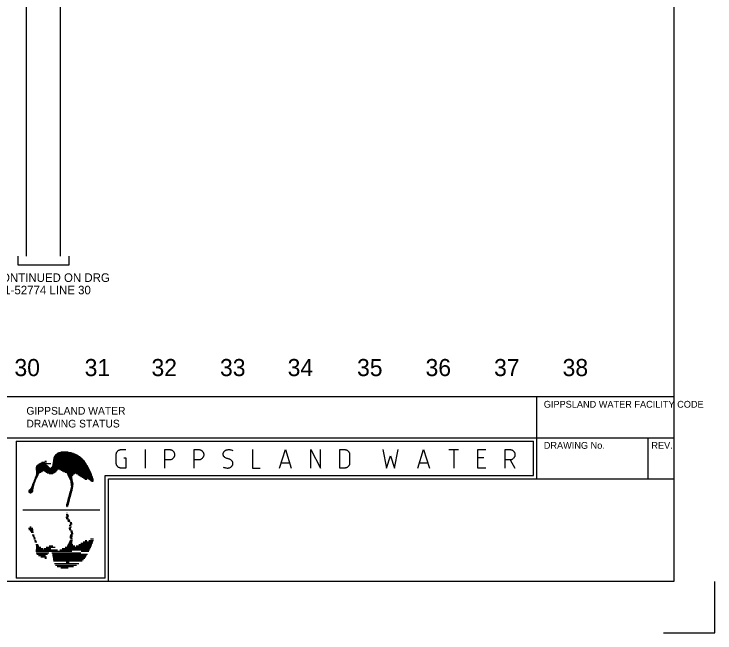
# Model space of a CAD drawing. Extents: x 0 to 841, y 0 to 594.
# Drawn here: x 636.4 to 841, y 0 to 180.7 of the extents above; entities that cross this region are included whole.
import ezdxf

# ---------------------------------------------------------------- set-up
doc = ezdxf.new("R2010")
doc.units = 0
doc.layers.add('A1BORDER', color=7, linetype='Continuous')
doc.layers.add('Level 1', color=7, linetype='Continuous')

msp = doc.modelspace()

# ---------------------------------------------------------------- linework, layer by layer
at = {"layer": 'A1BORDER'}
for p, q in [((829, 581), (829, 15)), ((592.5, 69), (829, 69)), ((789, 45), (789, 69)), ((28, 57), (829, 57)), ((637, 56), (788, 56)), ((637, 56), (637, 16)), ((788, 46), (788, 56)), ((821.5, 45), (821.5, 57)), ((648.03, 51.32), (655.85, 51.32)), ((648.12, 51.52), (655.59, 51.52)), ((648.23, 51.72), (655.31, 51.72)), ((648.37, 51.92), (655, 51.92)), ((648.53, 52.12), (654.64, 52.12)), ((648.74, 52.32), (654.24, 52.32)), ((649.02, 52.52), (653.76, 52.52)), ((649.39, 52.72), (653.15, 52.72)), ((650.01, 52.92), (652.2, 52.92)), ((643.26, 49.12), (645.9, 49.12)), ((643.54, 49.32), (645.57, 49.32)), ((643.85, 49.52), (647.09, 49.52)), ((644.18, 49.72), (645.89, 49.72)), ((644.54, 49.92), (645.36, 49.92)), ((645.37, 50.12), (645.86, 50.12)), ((647.63, 49.12), (657.68, 49.12)), ((647.66, 49.32), (657.57, 49.32)), ((647.69, 49.52), (657.44, 49.52)), ((647.71, 49.72), (657.31, 49.72)), ((647.75, 49.92), (657.17, 49.92)), ((647.78, 50.12), (657.02, 50.12)), ((647.81, 50.32), (656.86, 50.32)), ((647.85, 50.52), (656.69, 50.52)), ((647.88, 50.72), (656.5, 50.72)), ((647.91, 50.92), (656.3, 50.92)), ((647.96, 51.12), (656.08, 51.12)), ((642.73, 48.12), (658.25, 48.12)), ((642.74, 47.92), (658.35, 47.92)), ((642.75, 48.32), (646.79, 48.32)), ((642.79, 47.72), (649.08, 47.72)), ((642.81, 48.52), (646.55, 48.52)), ((642.83, 47.52), (648.95, 47.52)), ((642.85, 47.31), (644.88, 47.31)), ((642.87, 47.12), (644.57, 47.12)), ((642.9, 48.72), (646.37, 48.72)), ((643.04, 48.92), (646.16, 48.92)), ((645.14, 47.31), (648.83, 47.31)), ((645.49, 47.12), (648.67, 47.12)), ((647.19, 48.32), (658.14, 48.32)), ((647.42, 48.52), (658.03, 48.52)), ((647.54, 48.72), (657.92, 48.72)), ((647.61, 48.92), (657.8, 48.92)), ((649.72, 47.72), (658.45, 47.72)), ((650.12, 47.52), (658.55, 47.52)), ((650.48, 47.31), (658.64, 47.31)), ((650.87, 47.12), (658.73, 47.12)), ((642.43, 45.12), (642.9, 45.12)), ((642.5, 45.32), (643, 45.32)), ((642.57, 45.52), (643.1, 45.52)), ((642.65, 45.72), (643.2, 45.72)), ((642.72, 45.92), (643.3, 45.92)), ((642.79, 46.12), (643.4, 46.12)), ((642.84, 46.32), (643.5, 46.32)), ((642.87, 46.52), (643.6, 46.52)), ((642.88, 46.92), (644.23, 46.92)), ((642.88, 46.72), (643.83, 46.72)), ((645.76, 46.92), (648.42, 46.92)), ((646.05, 46.72), (648.11, 46.72)), ((646.62, 46.52), (647.67, 46.52)), ((651.36, 46.92), (658.82, 46.92)), ((651.76, 46.72), (658.9, 46.72)), ((651.88, 46.52), (654.15, 46.52)), ((651.99, 46.32), (653.71, 46.32)), ((652.1, 46.12), (653.52, 46.12)), ((652.2, 45.92), (653.4, 45.92)), ((652.31, 45.72), (653.33, 45.72)), ((652.41, 45.52), (653.31, 45.52)), ((652.5, 45.32), (653.34, 45.32)), ((652.6, 45.12), (653.38, 45.12)), ((654.57, 46.52), (658.99, 46.52)), ((655, 46.32), (659.07, 46.32)), ((655.31, 46.12), (659.14, 46.12)), ((655.62, 45.92), (659.22, 45.92)), ((655.93, 45.72), (659.29, 45.72)), ((656.24, 45.52), (659.35, 45.52)), ((656.55, 45.32), (659.42, 45.32)), ((656.86, 45.12), (657.74, 45.12)), ((657.91, 45.12), (659.48, 45.12)), ((663, 46), (788, 46)), ((663, 16), (663, 46)), ((641.64, 43.12), (642.25, 43.12)), ((641.73, 43.32), (642.3, 43.32)), ((641.82, 43.51), (642.35, 43.51)), ((641.91, 43.72), (642.41, 43.72)), ((641.99, 43.92), (642.48, 43.92)), ((642.06, 44.12), (642.55, 44.12)), ((642.13, 44.32), (642.62, 44.32)), ((642.21, 44.52), (642.69, 44.52)), ((642.28, 44.72), (642.76, 44.72)), ((642.35, 44.92), (642.83, 44.92)), ((652.69, 44.92), (653.41, 44.92)), ((652.78, 44.72), (653.44, 44.72)), ((652.83, 44.52), (653.48, 44.52)), ((652.86, 44.32), (653.53, 44.32)), ((652.89, 44.12), (653.57, 44.12)), ((652.91, 43.92), (653.62, 43.92)), ((652.94, 43.72), (653.67, 43.72)), ((652.97, 43.51), (653.71, 43.51)), ((653, 43.32), (653.69, 43.32)), ((653.02, 43.12), (653.67, 43.12)), ((657.17, 44.92), (657.68, 44.92)), ((657.51, 44.72), (657.54, 44.72)), ((658.19, 44.92), (659.54, 44.92)), ((658.47, 44.72), (659.59, 44.72)), ((658.75, 44.52), (659.58, 44.52)), ((659.02, 44.32), (659.47, 44.32)), ((664, 45), (829, 45)), ((664, 15), (664, 45)), ((640.62, 41.32), (641.88, 41.32)), ((640.63, 41.52), (641.93, 41.52)), ((640.72, 41.12), (641.73, 41.12)), ((640.73, 41.72), (641.95, 41.72)), ((640.9, 41.92), (641.97, 41.92)), ((641.1, 42.12), (642, 42.12)), ((641.25, 42.31), (642.04, 42.31)), ((641.37, 42.52), (642.09, 42.52)), ((641.46, 42.72), (642.15, 42.72)), ((641.55, 42.92), (642.2, 42.92)), ((652.63, 41.12), (653.26, 41.12)), ((652.68, 41.32), (653.31, 41.32)), ((652.74, 41.52), (653.37, 41.52)), ((652.79, 41.72), (653.41, 41.72)), ((652.85, 41.92), (653.45, 41.92)), ((652.9, 42.12), (653.49, 42.12)), ((652.95, 42.31), (653.53, 42.31)), ((652.99, 42.52), (653.57, 42.52)), ((653.03, 42.72), (653.61, 42.72)), ((653.05, 42.92), (653.64, 42.92)), ((641.03, 40.92), (641.43, 40.92)), ((652.03, 38.92), (652.66, 38.92)), ((652.09, 39.12), (652.72, 39.12)), ((652.14, 39.32), (652.77, 39.32)), ((652.2, 39.52), (652.82, 39.52)), ((652.25, 39.72), (652.88, 39.72)), ((652.3, 39.92), (652.93, 39.92)), ((652.36, 40.12), (652.99, 40.12)), ((652.41, 40.32), (653.04, 40.32)), ((652.47, 40.52), (653.1, 40.52)), ((652.52, 40.72), (653.15, 40.72)), ((652.57, 40.92), (653.2, 40.92)), ((651.63, 37.32), (652.23, 37.32)), ((651.64, 37.12), (652.17, 37.12)), ((651.65, 37.52), (652.28, 37.52)), ((651.71, 37.72), (652.34, 37.72)), ((651.76, 37.92), (652.39, 37.92)), ((651.79, 36.92), (651.9, 36.92)), ((651.82, 38.12), (652.44, 38.12)), ((651.87, 38.32), (652.5, 38.32)), ((651.92, 38.52), (652.55, 38.52)), ((651.98, 38.72), (652.61, 38.72)), ((638.93, 35.98), (661.47, 35.98)), ((651.79, 35.04), (651.9, 35.04)), ((651.54, 33.84), (652.17, 33.84)), ((651.63, 34.64), (652.23, 34.64)), ((651.65, 33.44), (652.28, 33.44)), ((651.71, 34.24), (652.34, 34.24)), ((652.03, 33.04), (652.66, 33.04)), ((641.03, 31.04), (641.43, 31.04)), ((652.14, 32.64), (652.77, 32.64)), ((652.47, 31.44), (653.1, 31.44)), ((652.57, 31.04), (653.2, 31.04)), ((652.66, 32.24), (653.29, 32.24)), ((652.77, 31.84), (653.4, 31.84)), ((640.62, 30.64), (641.88, 30.64)), ((640.73, 30.24), (641.95, 30.24)), ((641.1, 29.84), (642, 29.84)), ((641.37, 29.44), (642.09, 29.44)), ((652.34, 30.64), (652.97, 30.64)), ((652.45, 30.24), (653.07, 30.24)), ((652.9, 29.84), (653.49, 29.84)), ((652.99, 29.44), (653.57, 29.44)), ((653.05, 29.04), (653.64, 29.04)), ((641.73, 28.64), (642.3, 28.64)), ((641.91, 28.24), (642.41, 28.24)), ((642.06, 27.84), (642.55, 27.84)), ((642.21, 27.44), (642.69, 27.44)), ((642.35, 27.04), (642.83, 27.04)), ((642.5, 26.64), (643, 26.64)), ((652.5, 26.64), (653.34, 26.64)), ((652.66, 27.84), (653.35, 27.84)), ((652.69, 27.04), (653.41, 27.04)), ((652.72, 28.24), (653.44, 28.24)), ((652.77, 28.64), (653.46, 28.64)), ((652.83, 27.44), (653.48, 27.44)), ((656.55, 26.64), (659.42, 26.64)), ((657.17, 27.04), (657.68, 27.04)), ((658.19, 27.04), (659.54, 27.04)), ((658.75, 27.44), (659.58, 27.44)), ((642.79, 25.84), (643.4, 25.84)), ((642.85, 24.65), (644.88, 24.65)), ((642.87, 25.44), (643.6, 25.44)), ((642.88, 25.04), (644.23, 25.04)), ((645.14, 24.65), (647.18, 24.65)), ((645.76, 25.04), (648.42, 25.04)), ((646.62, 25.44), (647.67, 25.44)), ((650.48, 24.65), (658.64, 24.65)), ((651.36, 25.04), (658.82, 25.04)), ((651.88, 25.44), (654.15, 25.44)), ((652.1, 25.84), (653.52, 25.84)), ((652.31, 26.24), (653.33, 26.24)), ((654.57, 25.44), (658.99, 25.44)), ((655.31, 25.84), (659.14, 25.84)), ((655.93, 26.24), (659.29, 26.24)), ((642.73, 23.84), (653.27, 23.84)), ((642.79, 24.24), (649.08, 24.24)), ((642.81, 23.44), (646.55, 23.44)), ((643.04, 23.04), (646.16, 23.04)), ((643.54, 22.64), (645.57, 22.64)), ((647.42, 23.44), (655.89, 23.44)), ((647.61, 23.04), (657.8, 23.04)), ((647.66, 22.64), (657.57, 22.64)), ((649.72, 24.24), (658.45, 24.24)), ((655.94, 23.84), (658.25, 23.84)), ((644.18, 22.24), (645.89, 22.24)), ((645.37, 21.84), (645.86, 21.84)), ((647.71, 22.24), (657.31, 22.24)), ((647.78, 21.84), (657.02, 21.84)), ((647.85, 21.44), (656.69, 21.44)), ((647.91, 21.04), (656.3, 21.04)), ((651.57, 20.64), (652.44, 20.64)), ((648.23, 20.24), (655.31, 20.24)), ((648.53, 19.84), (654.64, 19.84)), ((649.02, 19.44), (653.76, 19.44)), ((650.01, 19.04), (652.2, 19.04)), ((829, 15), (28, 15)), ((663, 16), (637, 16)), ((829, 15), (829, 15)), ((841, 0), (841, 15)), ((826, 0), (841, 0))]:
    msp.add_line(p, q, dxfattribs=at)
for points in [[(668.49, 51.15), (669.06, 51.15), (669.06, 48.16), (667.64, 48.16), (667.51, 48.16), (667.39, 48.18), (667.28, 48.21), (667.15, 48.25), (667.04, 48.3), (666.93, 48.36), (666.82, 48.43), (666.73, 48.51), (666.64, 48.6), (666.55, 48.7), (666.48, 48.8), (666.41, 48.91), (666.35, 49.02), (666.31, 49.14), (666.27, 49.27), (666.24, 49.39), (666.22, 49.52), (666.22, 49.66), (666.22, 52.05), (666.22, 52.18), (666.24, 52.31), (666.27, 52.43), (666.31, 52.56), (666.35, 52.67), (666.41, 52.79), (666.48, 52.9), (666.55, 53), (666.64, 53.1), (666.73, 53.19), (666.82, 53.27), (666.93, 53.34), (667.04, 53.4), (667.15, 53.45), (667.28, 53.49), (667.39, 53.52), (667.51, 53.54), (667.64, 53.54), (669.06, 53.54)], [(674.74, 48.16), (674.74, 53.54)], [(680.42, 48.16), (680.42, 53.54), (681.84, 53.54), (681.96, 53.54), (682.08, 53.52), (682.2, 53.49), (682.32, 53.45), (682.43, 53.4), (682.54, 53.34), (682.65, 53.27), (682.74, 53.19), (682.84, 53.1), (682.92, 53), (682.99, 52.9), (683.06, 52.79), (683.12, 52.67), (683.17, 52.56), (683.21, 52.43), (683.23, 52.31), (683.25, 52.18), (683.26, 52.05), (683.25, 51.91), (683.23, 51.78), (683.21, 51.66), (683.17, 51.53), (683.12, 51.42), (683.06, 51.3), (682.99, 51.19), (682.92, 51.09), (682.84, 50.99), (682.74, 50.9), (682.65, 50.82), (682.54, 50.75), (682.43, 50.69), (682.32, 50.64), (682.2, 50.6), (682.08, 50.57), (681.96, 50.55), (681.84, 50.55), (680.42, 50.55)], [(688.93, 48.16), (688.93, 53.54), (690.35, 53.54), (690.47, 53.54), (690.59, 53.52), (690.71, 53.49), (690.83, 53.45), (690.94, 53.4), (691.05, 53.34), (691.16, 53.27), (691.26, 53.19), (691.35, 53.1), (691.43, 53), (691.51, 52.9), (691.57, 52.79), (691.63, 52.67), (691.68, 52.56), (691.72, 52.43), (691.75, 52.31), (691.76, 52.18), (691.77, 52.05), (691.76, 51.91), (691.75, 51.78), (691.72, 51.66), (691.68, 51.53), (691.63, 51.42), (691.57, 51.3), (691.51, 51.19), (691.43, 51.09), (691.35, 50.99), (691.26, 50.9), (691.16, 50.82), (691.05, 50.75), (690.94, 50.69), (690.83, 50.64), (690.71, 50.6), (690.59, 50.57), (690.47, 50.55), (690.35, 50.55), (688.93, 50.55)], [(697.45, 48.46), (697.67, 48.36), (697.9, 48.27), (698.12, 48.21), (698.36, 48.17), (698.6, 48.16), (698.84, 48.16), (698.87, 48.16), (699.03, 48.18), (699.18, 48.21), (699.33, 48.26), (699.48, 48.32), (699.62, 48.4), (699.72, 48.46), (699.81, 48.53), (699.9, 48.61), (699.98, 48.69), (700.05, 48.78), (700.11, 48.88), (700.17, 48.99), (700.22, 49.09), (700.25, 49.21), (700.28, 49.32), (700.29, 49.36), (700.3, 49.44), (700.3, 49.52), (700.3, 49.61), (700.29, 49.69), (700.27, 49.77), (700.25, 49.86), (700.22, 49.93), (700.18, 50.01), (700.14, 50.09), (700.09, 50.15), (700.04, 50.21), (700.01, 50.25), (699.85, 50.39), (699.69, 50.51), (699.52, 50.61), (699.34, 50.7), (699.15, 50.78), (698.95, 50.83), (698.87, 50.85), (698.68, 50.9), (698.49, 50.96), (698.3, 51.04), (698.12, 51.14), (697.96, 51.26), (697.8, 51.39), (697.73, 51.45), (697.67, 51.51), (697.62, 51.57), (697.58, 51.64), (697.53, 51.71), (697.5, 51.79), (697.47, 51.87), (697.46, 51.95), (697.44, 52.04), (697.43, 52.12), (697.43, 52.21), (697.44, 52.29), (697.45, 52.35), (697.47, 52.46), (697.51, 52.58), (697.55, 52.69), (697.61, 52.79), (697.67, 52.89), (697.74, 52.99), (697.82, 53.07), (697.9, 53.15), (697.99, 53.23), (698.02, 53.24), (698.15, 53.33), (698.3, 53.4), (698.44, 53.45), (698.6, 53.5), (698.75, 53.52), (698.87, 53.54), (699.11, 53.55), (699.35, 53.53), (699.58, 53.49), (699.82, 53.43), (700.04, 53.35), (700.27, 53.25)], [(705.96, 53.54), (705.96, 48.16), (708.23, 48.16)], [(713.91, 48.16), (715.61, 53.54), (717.32, 48.16)], [(722.99, 48.16), (722.99, 53.54), (725.83, 48.16), (725.83, 53.54)], [(731.52, 48.16), (731.52, 53.54), (732.94, 53.54), (733.06, 53.54), (733.18, 53.52), (733.3, 53.49), (733.42, 53.45), (733.53, 53.4), (733.64, 53.34), (733.75, 53.27), (733.84, 53.19), (733.94, 53.1), (734.02, 53), (734.09, 52.9), (734.16, 52.79), (734.22, 52.67), (734.27, 52.56), (734.31, 52.43), (734.33, 52.31), (734.35, 52.18), (734.36, 52.05), (734.36, 49.66), (734.35, 49.52), (734.33, 49.39), (734.31, 49.27), (734.27, 49.14), (734.22, 49.02), (734.16, 48.91), (734.09, 48.8), (734.02, 48.7), (733.94, 48.6), (733.84, 48.51), (733.75, 48.43), (733.64, 48.36), (733.53, 48.3), (733.42, 48.25), (733.3, 48.21), (733.18, 48.18), (733.06, 48.16), (732.94, 48.16), (731.52, 48.16)], [(744.01, 53.54), (745.14, 48.16), (746.28, 51.75), (747.41, 48.16), (748.55, 53.54)], [(754.22, 48.16), (755.92, 53.54), (757.63, 48.16)], [(763.31, 53.54), (766.15, 53.54)], [(764.73, 53.54), (764.73, 48.16)], [(774.09, 48.16), (771.82, 48.16), (771.82, 53.54), (774.09, 53.54)], [(779.78, 48.16), (779.78, 53.54), (781.2, 53.54), (781.32, 53.54), (781.44, 53.52), (781.56, 53.49), (781.68, 53.45), (781.79, 53.4), (781.9, 53.34), (782.01, 53.27), (782.1, 53.19), (782.2, 53.1), (782.28, 53), (782.35, 52.9), (782.42, 52.79), (782.48, 52.67), (782.53, 52.56), (782.56, 52.43), (782.59, 52.31), (782.61, 52.18), (782.61, 52.05), (782.61, 51.91), (782.59, 51.78), (782.56, 51.66), (782.53, 51.53), (782.48, 51.42), (782.42, 51.3), (782.35, 51.19), (782.28, 51.09), (782.2, 50.99), (782.1, 50.9), (782.01, 50.82), (781.9, 50.75), (781.79, 50.69), (781.68, 50.64), (781.56, 50.6), (781.44, 50.57), (781.32, 50.55), (781.2, 50.55), (779.78, 50.55)], [(714.48, 49.66), (716.75, 49.66)], [(754.79, 49.66), (757.06, 49.66)], [(773.53, 51.15), (771.82, 51.15)], [(781.2, 50.55), (782.61, 48.16)]]:
    msp.add_lwpolyline(points, dxfattribs=at)
at = {"layer": 'Level 1'}
for p, q in [((640, 110), (640, 545)), ((650, 110), (650, 347.5))]:
    msp.add_line(p, q, dxfattribs=at)
msp.add_lwpolyline([(637.5, 110), (637.5, 107.5), (652.5, 107.5), (652.5, 110)], dxfattribs=at)

# ---------------------------------------------------------------- texts
at = {"layer": 'A1BORDER'}
for s, height, p in [('GIPPSLAND WATER FACILITY CODE', 2, (791.03, 65.77)), ('GIPPSLAND WATER', 2.25, (640, 63.75)), ('DRAWING STATUS', 2.25, (640, 60)), ('DRAWING No.', 2, (791.03, 53.77)), ('REV.', 2, (822.43, 53.77))]:
    msp.add_text(s, height=height, dxfattribs=at).set_placement(p)
at = {"layer": 'Level 1'}
for s, height, p in [('CONTINUED ON DRG', 2.5, (630.18, 102.5)), ('A1-52774 LINE 30', 2.5, (631.3, 98.88)), ('30', 5, (636.52, 75)), ('31', 5, (657.01, 75)), ('32', 5, (676.52, 75)), ('33', 5, (696.52, 75)), ('34', 5, (716.26, 75)), ('35', 5, (736.52, 75)), ('36', 5, (756.52, 75)), ('37', 5, (776.52, 75)), ('38', 5, (796.52, 75))]:
    msp.add_text(s, height=height, dxfattribs=at).set_placement(p)

doc.saveas('drawing.dxf')
